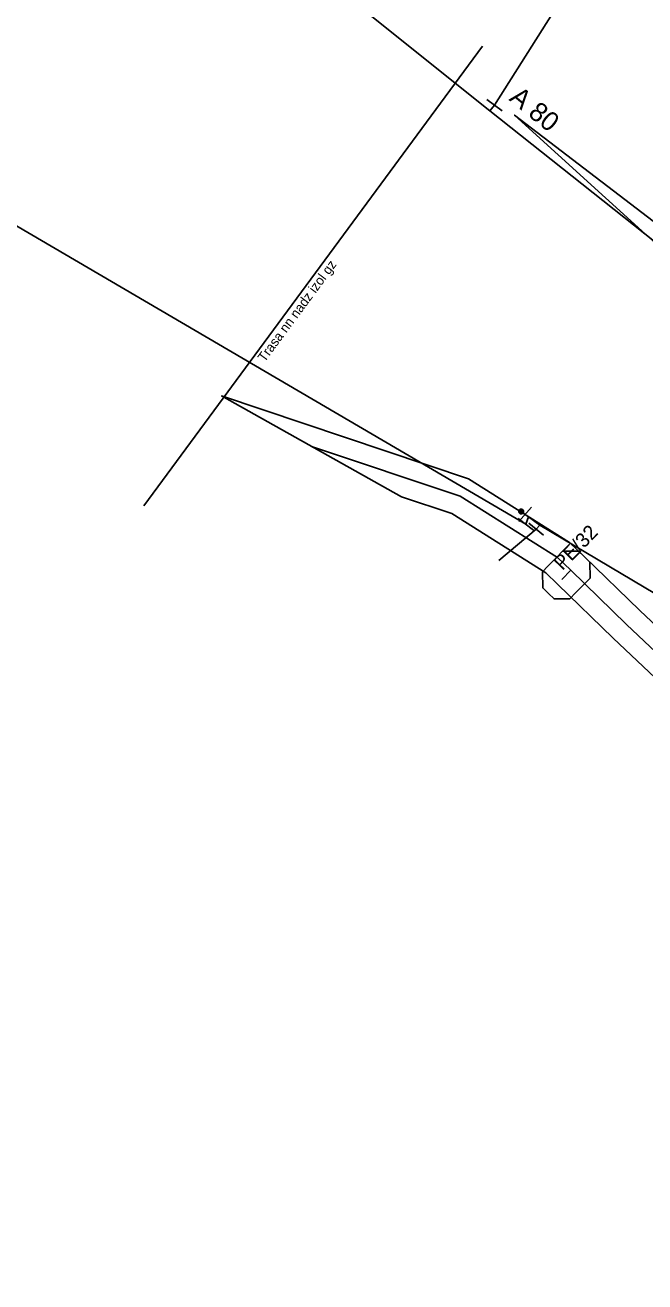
# Model space of a CAD drawing. Extents: x -743072 to -742584, y -978827 to -978325.
# Drawn here: x -742951.5 to -742919.2, y -978491.4 to -978426 of the extents above; entities that cross this region are included whole.
import ezdxf

# ---------------------------------------------------------------- set-up
doc = ezdxf.new("R2010")
doc.units = 0
for name, color, linetype in [('IS_CEZ_NN_nadz', 7, 'Continuous'), ('IS_GasNet_ochr pasmo', 7, 'Continuous'), ('IS_GasNet_plyn STL', 7, 'Continuous'), ('IS_popis_CEZ', 7, 'Continuous'), ('IS_popis_GasNet', 7, 'Continuous'), ('IS_popis_ScVK', 7, 'Continuous'), ('IS_ScVK_Kanal_dest', 7, 'Continuous'), ('IS_ScVK_Vodovod', 7, 'Continuous')]:
    doc.layers.add(name, color=color, linetype=linetype)

msp = doc.modelspace()

# ---------------------------------------------------------------- linework, layer by layer
at = {"layer": 'IS_CEZ_NN_nadz'}
msp.add_lwpolyline([(-742927.69, -978427.04), (-742945.35, -978450.99)], dxfattribs=at)
at = {"layer": 'IS_GasNet_ochr pasmo'}
for points in [[(-742914.264, -978441.318), (-742926.022, -978430.64), (-742905.159, -978446.574), (-742899.146, -978451.799), (-742893.056, -978457.091), (-742892.46, -978457.608), (-742890.34, -978459.488), (-742885.549, -978463.651), (-742875.072, -978475.552), (-742884.039, -978467.612), (-742891.66, -978460.992), (-742893.78, -978459.112), (-742894.368, -978458.601), (-742900.458, -978453.309), (-742912.165, -978443.135)], [(-742922.09, -978454.743), (-742922.379, -978455.04), (-742922.848, -978455.523), (-742923.136, -978455.82), (-742923.965, -978455.832), (-742924.262, -978455.543), (-742924.559, -978455.255), (-742924.571, -978454.426), (-742924.282, -978454.129), (-742923.813, -978453.646), (-742923.525, -978453.349), (-742922.696, -978453.337), (-742922.399, -978453.626), (-742922.102, -978453.914)]]:
    msp.add_lwpolyline(points, close=True, dxfattribs=at)
msp.add_lwpolyline([(-742884.489, -978493.578), (-742895.323, -978483.286), (-742896.346, -978482.026), (-742897.393, -978480.896), (-742902.083, -978475.831), (-742905.299, -978472.575), (-742920.881, -978457.883), (-742923.792, -978455.061), (-742924.401, -978454.471), (-742929.291, -978451.39), (-742931.913, -978450.512), (-742941.288, -978445.265), (-742928.429, -978449.57), (-742923.159, -978452.889), (-742922.4, -978453.625), (-742919.499, -978456.437), (-742903.901, -978471.145), (-742900.637, -978474.449), (-742895.925, -978479.536), (-742894.834, -978480.714), (-742882.031, -978496.481)], dxfattribs=at)
at = {"layer": 'IS_GasNet_plyn STL'}
for points in [[(-742936.599, -978447.889), (-742928.86, -978450.48), (-742923.78, -978453.68), (-742923.096, -978454.343), (-742920.19, -978457.16), (-742904.6, -978471.86), (-742901.36, -978475.14), (-742896.659, -978480.216), (-742895.59, -978481.37), (-742889.684, -978488.643)], [(-742923.096, -978454.343), (-742923.565, -978454.826)]]:
    msp.add_lwpolyline(points, dxfattribs=at)
at = {"layer": 'IS_ScVK_Kanal_dest'}
for points in [[(-742927.308, -978430.422), (-742927.07, -978430.12)], [(-742925.477, -978451.431), (-742925.677, -978451.278)], [(-742925.299, -978451.559), (-742925.438, -978451.947)], [(-742924.708, -978451.984), (-742924.899, -978452.199)]]:
    msp.add_lwpolyline(points, dxfattribs=at)
at = {"layer": 'IS_ScVK_Vodovod'}
for points in [[(-742977.649, -978388.53), (-742976.664, -978389.595), (-742974.357, -978391.436), (-742948.728, -978413.286), (-742927.308, -978430.422), (-742902.077, -978450.432), (-742883.738, -978468.975), (-742876.53, -978475.383)], [(-742925.438, -978451.947), (-743009.893, -978402.51), (-743030.46, -978405.59)], [(-742927.07, -978430.12), (-742920.691, -978420.03)], [(-742927.471, -978429.821), (-742926.669, -978430.419)], [(-742925.147, -978451.054), (-742925.806, -978451.806)], [(-742925.803, -978451.278), (-742925.803, -978451.291), (-742925.801, -978451.304), (-742925.798, -978451.317), (-742925.793, -978451.329), (-742925.787, -978451.341), (-742925.78, -978451.352), (-742925.772, -978451.362), (-742925.762, -978451.372), (-742925.752, -978451.38), (-742925.741, -978451.387), (-742925.729, -978451.393), (-742925.717, -978451.398), (-742925.704, -978451.401), (-742925.691, -978451.403), (-742925.678, -978451.405), (-742925.665, -978451.404), (-742925.652, -978451.402), (-742925.639, -978451.399), (-742925.627, -978451.394), (-742925.615, -978451.388), (-742925.604, -978451.381), (-742925.594, -978451.373), (-742925.584, -978451.363), (-742925.576, -978451.353), (-742925.569, -978451.342), (-742925.563, -978451.33), (-742925.558, -978451.318), (-742925.555, -978451.305), (-742925.553, -978451.292), (-742925.551, -978451.279), (-742925.552, -978451.266), (-742925.554, -978451.253), (-742925.557, -978451.24), (-742925.562, -978451.228), (-742925.568, -978451.216), (-742925.575, -978451.205), (-742925.583, -978451.195), (-742925.593, -978451.185), (-742925.603, -978451.177), (-742925.614, -978451.17), (-742925.626, -978451.164), (-742925.638, -978451.159), (-742925.651, -978451.156), (-742925.664, -978451.154), (-742925.677, -978451.153), (-742925.69, -978451.153), (-742925.703, -978451.155), (-742925.716, -978451.158), (-742925.728, -978451.163), (-742925.74, -978451.169), (-742925.751, -978451.176), (-742925.761, -978451.184), (-742925.771, -978451.194), (-742925.779, -978451.204), (-742925.786, -978451.215), (-742925.792, -978451.227), (-742925.797, -978451.239), (-742925.8, -978451.252), (-742925.802, -978451.265), (-742925.803, -978451.278)], [(-742925.783, -978451.278), (-742925.784, -978451.289), (-742925.782, -978451.3), (-742925.779, -978451.311), (-742925.775, -978451.321), (-742925.77, -978451.331), (-742925.764, -978451.34), (-742925.757, -978451.349), (-742925.749, -978451.357), (-742925.74, -978451.364), (-742925.731, -978451.37), (-742925.721, -978451.375), (-742925.711, -978451.379), (-742925.7, -978451.382), (-742925.689, -978451.385), (-742925.678, -978451.385), (-742925.667, -978451.385), (-742925.656, -978451.383), (-742925.645, -978451.38), (-742925.635, -978451.376), (-742925.625, -978451.371), (-742925.616, -978451.365), (-742925.607, -978451.358), (-742925.599, -978451.35), (-742925.592, -978451.341), (-742925.586, -978451.332), (-742925.581, -978451.322), (-742925.577, -978451.312), (-742925.574, -978451.301), (-742925.572, -978451.29), (-742925.571, -978451.279), (-742925.571, -978451.268), (-742925.573, -978451.257), (-742925.576, -978451.246), (-742925.58, -978451.236), (-742925.585, -978451.226), (-742925.591, -978451.217), (-742925.598, -978451.208), (-742925.606, -978451.2), (-742925.615, -978451.193), (-742925.624, -978451.187), (-742925.634, -978451.182), (-742925.644, -978451.178), (-742925.655, -978451.175), (-742925.666, -978451.173), (-742925.677, -978451.173), (-742925.688, -978451.172), (-742925.699, -978451.174), (-742925.71, -978451.177), (-742925.72, -978451.181), (-742925.73, -978451.186), (-742925.739, -978451.192), (-742925.748, -978451.199), (-742925.756, -978451.207), (-742925.763, -978451.216), (-742925.769, -978451.225), (-742925.774, -978451.235), (-742925.778, -978451.245), (-742925.781, -978451.256), (-742925.783, -978451.267), (-742925.783, -978451.278)], [(-742925.764, -978451.278), (-742925.764, -978451.287), (-742925.763, -978451.296), (-742925.76, -978451.305), (-742925.757, -978451.313), (-742925.753, -978451.321), (-742925.748, -978451.329), (-742925.742, -978451.336), (-742925.736, -978451.342), (-742925.729, -978451.348), (-742925.721, -978451.353), (-742925.713, -978451.357), (-742925.705, -978451.36), (-742925.696, -978451.363), (-742925.687, -978451.364), (-742925.678, -978451.366), (-742925.669, -978451.365), (-742925.66, -978451.364), (-742925.651, -978451.361), (-742925.643, -978451.358), (-742925.635, -978451.354), (-742925.627, -978451.349), (-742925.62, -978451.343), (-742925.614, -978451.337), (-742925.608, -978451.33), (-742925.603, -978451.322), (-742925.599, -978451.314), (-742925.596, -978451.306), (-742925.593, -978451.297), (-742925.592, -978451.288), (-742925.59, -978451.279), (-742925.591, -978451.27), (-742925.592, -978451.261), (-742925.595, -978451.252), (-742925.598, -978451.244), (-742925.602, -978451.236), (-742925.607, -978451.228), (-742925.613, -978451.221), (-742925.619, -978451.215), (-742925.626, -978451.209), (-742925.634, -978451.204), (-742925.642, -978451.2), (-742925.65, -978451.197), (-742925.659, -978451.194), (-742925.668, -978451.193), (-742925.677, -978451.192), (-742925.686, -978451.192), (-742925.695, -978451.193), (-742925.704, -978451.196), (-742925.712, -978451.199), (-742925.72, -978451.203), (-742925.728, -978451.208), (-742925.735, -978451.214), (-742925.741, -978451.22), (-742925.747, -978451.227), (-742925.752, -978451.235), (-742925.756, -978451.243), (-742925.759, -978451.251), (-742925.762, -978451.26), (-742925.763, -978451.269), (-742925.764, -978451.278)], [(-742925.744, -978451.278), (-742925.744, -978451.285), (-742925.743, -978451.292), (-742925.742, -978451.299), (-742925.739, -978451.305), (-742925.736, -978451.311), (-742925.732, -978451.317), (-742925.728, -978451.323), (-742925.723, -978451.328), (-742925.717, -978451.332), (-742925.711, -978451.336), (-742925.705, -978451.339), (-742925.699, -978451.342), (-742925.692, -978451.343), (-742925.685, -978451.346), (-742925.678, -978451.346), (-742925.671, -978451.346), (-742925.664, -978451.344), (-742925.657, -978451.343), (-742925.651, -978451.34), (-742925.644, -978451.337), (-742925.639, -978451.333), (-742925.633, -978451.329), (-742925.628, -978451.324), (-742925.624, -978451.318), (-742925.62, -978451.312), (-742925.617, -978451.306), (-742925.614, -978451.3), (-742925.612, -978451.293), (-742925.611, -978451.286), (-742925.61, -978451.279), (-742925.61, -978451.272), (-742925.611, -978451.265), (-742925.613, -978451.258), (-742925.616, -978451.252), (-742925.619, -978451.245), (-742925.623, -978451.24), (-742925.627, -978451.234), (-742925.632, -978451.229), (-742925.638, -978451.225), (-742925.643, -978451.221), (-742925.65, -978451.218), (-742925.656, -978451.215), (-742925.663, -978451.213), (-742925.67, -978451.212), (-742925.677, -978451.212), (-742925.684, -978451.212), (-742925.691, -978451.212), (-742925.698, -978451.214), (-742925.704, -978451.217), (-742925.71, -978451.22), (-742925.716, -978451.224), (-742925.722, -978451.228), (-742925.727, -978451.233), (-742925.731, -978451.239), (-742925.735, -978451.244), (-742925.738, -978451.251), (-742925.741, -978451.257), (-742925.742, -978451.264), (-742925.744, -978451.271), (-742925.744, -978451.278)], [(-742925.724, -978451.278), (-742925.724, -978451.283), (-742925.724, -978451.288), (-742925.723, -978451.293), (-742925.721, -978451.297), (-742925.719, -978451.302), (-742925.716, -978451.306), (-742925.713, -978451.309), (-742925.709, -978451.313), (-742925.706, -978451.316), (-742925.702, -978451.319), (-742925.697, -978451.321), (-742925.693, -978451.323), (-742925.688, -978451.324), (-742925.683, -978451.326), (-742925.678, -978451.326), (-742925.673, -978451.326), (-742925.668, -978451.325), (-742925.663, -978451.324), (-742925.659, -978451.322), (-742925.654, -978451.32), (-742925.65, -978451.317), (-742925.646, -978451.314), (-742925.643, -978451.31), (-742925.64, -978451.307), (-742925.637, -978451.303), (-742925.635, -978451.298), (-742925.633, -978451.294), (-742925.632, -978451.289), (-742925.631, -978451.284), (-742925.63, -978451.279), (-742925.63, -978451.274), (-742925.631, -978451.269), (-742925.632, -978451.264), (-742925.634, -978451.26), (-742925.636, -978451.255), (-742925.639, -978451.251), (-742925.642, -978451.247), (-742925.645, -978451.244), (-742925.649, -978451.241), (-742925.653, -978451.238), (-742925.658, -978451.236), (-742925.662, -978451.234), (-742925.667, -978451.233), (-742925.672, -978451.232), (-742925.677, -978451.232), (-742925.682, -978451.232), (-742925.687, -978451.233), (-742925.692, -978451.233), (-742925.696, -978451.235), (-742925.701, -978451.237), (-742925.705, -978451.24), (-742925.708, -978451.243), (-742925.712, -978451.246), (-742925.715, -978451.25), (-742925.718, -978451.254), (-742925.72, -978451.259), (-742925.722, -978451.263), (-742925.723, -978451.268), (-742925.724, -978451.273), (-742925.724, -978451.278)], [(-742925.704, -978451.278), (-742925.704, -978451.281), (-742925.705, -978451.284), (-742925.704, -978451.286), (-742925.703, -978451.289), (-742925.702, -978451.292), (-742925.7, -978451.294), (-742925.698, -978451.296), (-742925.696, -978451.298), (-742925.694, -978451.3), (-742925.692, -978451.302), (-742925.689, -978451.304), (-742925.686, -978451.305), (-742925.684, -978451.305), (-742925.681, -978451.306), (-742925.678, -978451.306), (-742925.675, -978451.306), (-742925.672, -978451.306), (-742925.669, -978451.305), (-742925.667, -978451.304), (-742925.664, -978451.303), (-742925.662, -978451.301), (-742925.659, -978451.299), (-742925.657, -978451.297), (-742925.656, -978451.295), (-742925.654, -978451.293), (-742925.653, -978451.29), (-742925.651, -978451.287), (-742925.651, -978451.285), (-742925.65, -978451.282), (-742925.649, -978451.279), (-742925.65, -978451.276), (-742925.65, -978451.273), (-742925.651, -978451.27), (-742925.652, -978451.268), (-742925.653, -978451.265), (-742925.655, -978451.263), (-742925.656, -978451.26), (-742925.658, -978451.258), (-742925.661, -978451.257), (-742925.663, -978451.255), (-742925.666, -978451.254), (-742925.668, -978451.253), (-742925.671, -978451.252), (-742925.674, -978451.252), (-742925.677, -978451.251), (-742925.68, -978451.252), (-742925.683, -978451.251), (-742925.685, -978451.253), (-742925.688, -978451.253), (-742925.691, -978451.254), (-742925.693, -978451.256), (-742925.695, -978451.257), (-742925.697, -978451.259), (-742925.699, -978451.262), (-742925.701, -978451.264), (-742925.702, -978451.267), (-742925.703, -978451.269), (-742925.704, -978451.272), (-742925.704, -978451.275), (-742925.704, -978451.278)], [(-742925.685, -978451.278), (-742925.685, -978451.28), (-742925.685, -978451.28), (-742925.684, -978451.28), (-742925.684, -978451.282), (-742925.685, -978451.283), (-742925.683, -978451.283), (-742925.683, -978451.283), (-742925.683, -978451.285), (-742925.683, -978451.285), (-742925.682, -978451.286), (-742925.68, -978451.286), (-742925.68, -978451.286), (-742925.68, -978451.287), (-742925.678, -978451.287), (-742925.678, -978451.287), (-742925.677, -978451.287), (-742925.676, -978451.287), (-742925.676, -978451.286), (-742925.675, -978451.286), (-742925.673, -978451.286), (-742925.673, -978451.285), (-742925.673, -978451.285), (-742925.672, -978451.284), (-742925.672, -978451.284), (-742925.67, -978451.283), (-742925.67, -978451.282), (-742925.669, -978451.281), (-742925.669, -978451.281), (-742925.669, -978451.28), (-742925.669, -978451.279), (-742925.669, -978451.278), (-742925.669, -978451.277), (-742925.669, -978451.277), (-742925.67, -978451.276), (-742925.67, -978451.275), (-742925.671, -978451.274), (-742925.671, -978451.274), (-742925.672, -978451.273), (-742925.672, -978451.273), (-742925.673, -978451.272), (-742925.674, -978451.272), (-742925.675, -978451.271), (-742925.675, -978451.271), (-742925.676, -978451.271), (-742925.677, -978451.271), (-742925.678, -978451.271), (-742925.679, -978451.271), (-742925.679, -978451.271), (-742925.68, -978451.272), (-742925.681, -978451.271), (-742925.682, -978451.273), (-742925.682, -978451.273), (-742925.683, -978451.273), (-742925.683, -978451.273), (-742925.684, -978451.275), (-742925.684, -978451.276), (-742925.684, -978451.277), (-742925.685, -978451.277), (-742925.685, -978451.278), (-742925.685, -978451.278)], [(-742866.026, -978515.027), (-742875.324, -978505.832), (-742881.523, -978496.585), (-742891.202, -978483.542), (-742905.997, -978463.103), (-742924.708, -978451.984), (-742925.299, -978451.559), (-742925.477, -978451.431)], [(-742925.835, -978451.643), (-742925.041, -978452.25)], [(-742925.284, -978451.88), (-742924.514, -978452.518)], [(-742924.899, -978452.199), (-742926.847, -978453.834)]]:
    msp.add_lwpolyline(points, dxfattribs=at)

# ---------------------------------------------------------------- texts
at = {"layer": 'IS_popis_CEZ'}
msp.add_text('Trasa nn nadz izol gz', height=0.5, rotation=53.59607, dxfattribs=at).set_placement((-742939.045, -978443.534))
at = {"layer": 'IS_popis_GasNet'}
msp.add_text('PE/32', height=0.75, rotation=45.84252, dxfattribs=at).set_placement((-742923.53, -978454.385))
at = {"layer": 'IS_popis_ScVK'}
msp.add_text('A 80', height=1, rotation=321, dxfattribs=at).set_placement((-742926.353, -978429.842))

doc.saveas('drawing.dxf')
